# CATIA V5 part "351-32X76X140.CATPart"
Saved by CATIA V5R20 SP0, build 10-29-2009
Part number: 351-32X76X140
Definition: NONE
Nomenclature: 351-32X76X140
Source: Unknown
Description: 351-32X76X140
Bounding box of the stored display mesh (mm): x -7 to 133, y -22.5 to 22.5, z -22.5 to 22.5
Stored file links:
  C:\Users\Utente\Desktop\IO LAVORO\3D X SITO CF\X SITO\PLASTICA\351\351-32X76X140.CATPart
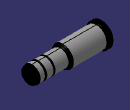
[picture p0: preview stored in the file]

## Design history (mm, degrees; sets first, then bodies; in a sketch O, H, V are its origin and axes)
Body1 "351-32X76X140" (main body)
  Solid1: solid without history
